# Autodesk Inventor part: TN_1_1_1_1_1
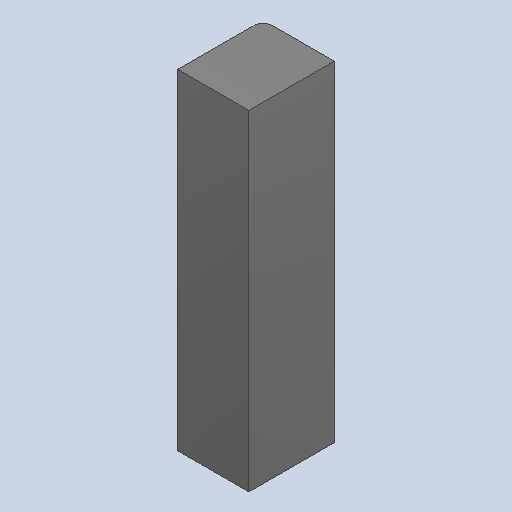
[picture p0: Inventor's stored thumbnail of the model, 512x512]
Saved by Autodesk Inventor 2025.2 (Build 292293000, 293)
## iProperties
Created: 2025-04
Part Number: TN_1_1_1_1_1
Material: Generic
Description: NOT SPECIFIED
Document SubType Name: Modeling
Designer: BennF
Density: 1 g/cm^3
Appearance: Default
Author: BennF
Revision Number: 2LAST_VERSION
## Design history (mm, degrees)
feature "Base1"
body "Solid1"
